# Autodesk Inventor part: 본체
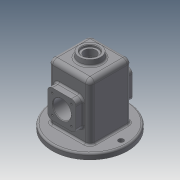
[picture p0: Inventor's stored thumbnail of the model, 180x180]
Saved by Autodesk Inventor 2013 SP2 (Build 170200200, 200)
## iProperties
Created: 2021-08
Part Number: 본체
Material: Generic
Document SubType Name: Modeling
Designer: kumcom13
Density: 1 g/cm^3
Author: kumcom13
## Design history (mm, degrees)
sketch "스케치1"
  geometry: L1 (-37, -55)-(37, -55); L2 (37, -55)-(37, 55); L3 (37, 55)-(-37, 55); L4 (-37, 55)-(-37, -55); L5 (-37, -55)-(37, 55); L6 (37, -55)-(-37, 55); 1 further point
  constraints: 12 end point, 2 midpoint, 2 parallel, 1 horizontal, 1 perpendicular
  dimensions: "d0" = 74 distance of L3.end L2.end; "d1" = 110 distance of L2.end L1.end
extrude "돌출1" new body sketch "스케치1" stored distance "d2" = 74; taper "d3" = 0 deg
feature "쉘1" dims "d4" = 5
sketch "스케치3"
  geometry: L1 (74, -74)-(74, 0) reference; L2 (0, 0)-(74, 0) reference; L3 (0, 0)-(0, -74) reference; L4 (74, -74)-(0, -74) reference; C1 r 67 at (37, -37); 1 further point
  constraints: 1 centre point, 1 coincident
  dimensions: "d5" = 134 diameter of C1
extrude "돌출2" join sketch "스케치3" distance "d6" = 10; taper "d7" = 0 deg
sketch "스케치4"
  geometry: C1 r 20 at (37, 37); 1 further point
  constraints: 1 centre point, 1 coincident
  dimensions: "d8" = 40 diameter of C1
extrude "돌출3" join sketch "스케치4" distance "d9" = 10; taper "d10" = -6 deg
sketch "스케치5"
  geometry: C1 r 18.949 at (0, 0) reference; 1 further point
  constraints: 1 coincident
hole "구멍1" sketch "스케치5" at (0, 0) diameter "d11" = 21; stored, may be unused: countersink angle "d15" = 90 deg, drill point angle "d17" = 0 deg; dims "d12" = 6, "d13" = 28, "d14" = 4, "d16" = 15
sketch "스케치6"
  geometry: L1 (67, -55)-(-67, -55) reference; L2 (-25, -25)-(25, -25); L3 (25, -25)-(25, 25); L4 (25, 25)-(-25, 25); L5 (-25, 25)-(-25, -25); L6 (-25, -25)-(25, 25); L7 (25, -25)-(-25, 25); 1 further point
  constraints: 12 end point, 2 midpoint, 2 parallel, 1 horizontal, 1 perpendicular
  dimensions: "d18" = 50 distance of L4.end L3.end; "d19" = 50 distance of L3.end L2.end
extrude "돌출4" join sketch "스케치6" distance "d20" = 13; taper "d21" = 0 deg
fillet "모깎기1" dims "d22" = 8
sketch "스케치7"
  geometry: C1 r 16 at (0, 0); 1 further point
  constraints: 1 centre point, 1 coincident
  dimensions: "d23" = 32 diameter of C1
extrude "돌출5" cut sketch "스케치7" stored distance "d24" = 13; taper "d25" = 0 deg
sketch "스케치8"
  geometry: A1 r 8 centre (-17, 17) between (-17, 25) and (-25, 17) reference; A2 r 8 centre (-17, -17) between (-25, -17) and (-17, -25) reference; A3 r 8 centre (17, -17) between (17, -25) and (25, -17) reference; A4 r 8 centre (17, 17) between (25, 17) and (17, 25) reference; 4 further points
  constraints: 4 coincident
hole "구멍2" sketch "스케치8" at (-17, 17), (17, 17), (17, -17), (-17, -17) diameter "d26" = 3.242; stored, may be unused: countersink angle "d30" = 90 deg, drill point angle "d32" = 118 deg; dims "d27" = 8, "d28" = 28, "d29" = 4, "d31" = 10
chamfer "모따기1" distance "d33" = 1; stored, may be unused: second distance "d34" = 2, angle "d35" = 45 deg
fillet "모깎기2" dims "d36" = 8
fillet "모깎기3" dims "d37" = 8
fillet "모깎기4" dims "d38" = 3
fillet "모깎기5" dims "d39" = 3
chamfer "모따기2" distance "d40" = 1; stored, may be unused: second distance "d41" = 2, angle "d42" = 45 deg
sketch "스케치9"
  geometry: L1 (40, -29)-(40, 29) reference; L2 (0, 0)-(-55, 0); L3 (0, 0)-(55, 0); C1 r 64 at (0, 0) reference; C2 r 4.5 at (-55, 0); C3 r 4.5 at (55, 0)
  constraints: 4 end point, 2 centre point, 2 coincident, 1 collinear, 1 perpendicular
  dimensions: "d43" = 55 distance of L2.start L2.end; "d44" = 55 distance of L2.start L3.end; "d45" = 9 diameter of C2; "d46" = 9 diameter of C3
extrude "돌출6" cut sketch "스케치9" stored distance "d47" = 13; taper "d48" = 0 deg
fillet "모깎기6" dims "d49" = 3
fillet "모깎기7" dims "d50" = 3
node "작업 평면1"
sketch "스케치10"
  geometry: C1 r 25 at (0, 0); 1 further point
  constraints: 1 centre point, 1 coincident
  dimensions: "d52" = 50 diameter of C1
extrude "돌출7" join sketch "스케치10" distance "d53" = 7; taper "d54" = 20 deg
sketch "스케치11"
  geometry: C1 r 16 at (0, 0) reference; C2 r 16 at (0, 0)
  constraints: 1 centre point, 1 coincident
  dimensions: "d55" = 32 diameter of C2
extrude "돌출8" cut sketch "스케치11" distance "d56" = 100; taper "d57" = 0 deg
sketch "스케치12"
  geometry: L1 (-18.949, 65)-(18.949, 65) reference; L2 (-37, 47)-(-37, -42) reference; 2 further points
  constraints: 1 other
  dimensions: "d58" = 28 distance from line of point (0, 37) L1; "d59" = 37 distance from line of point (0, 37) L2
feature "엠보싱1" sketch "스케치12" dims "d0" = 74, "d1" = 110, "d60" = 0.5, "d61" = 0
node "솔리드1"
mirror "대칭1"
mirror "대칭2"
other parameters: "d51" = -25
